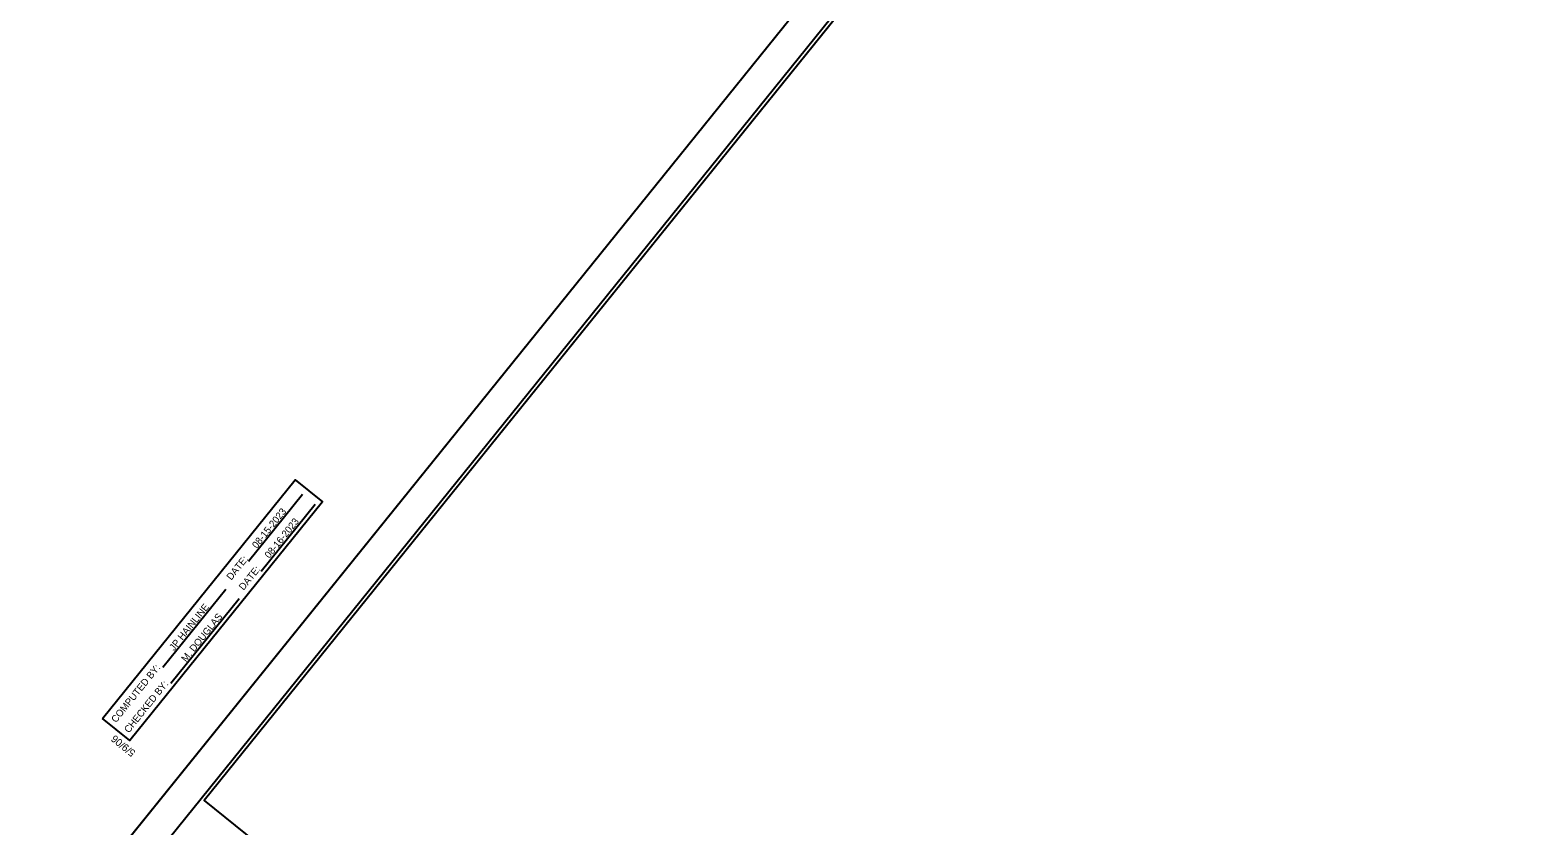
# Model space of a CAD drawing. Extents: x 1489015 to 1490928, y 499814 to 501978.
# Drawn here: x 1489015 to 1490091, y 500601 to 501169 of the extents above; entities that cross this region are included whole.
import ezdxf

# ---------------------------------------------------------------- set-up
doc = ezdxf.new("R2010")
doc.units = 0
for name, color, linetype in [('Sheet Clip Boundary CELL', 7, 'Continuous'), ('Sheet Cutting Line CELL', 7, 'Continuous'), ('Sheet Data Field CELL', 7, 'Continuous'), ('Sheet Plot Border Inside CELL', 7, 'Continuous'), ('Sheet Plot Border Outside CELL', 7, 'Continuous'), ('Sheet Summary Earthwork CELL', 7, 'Continuous')]:
    doc.layers.add(name, color=color, linetype=linetype)

msp = doc.modelspace()

# ---------------------------------------------------------------- linework, layer by layer
at = {"layer": 'Sheet Clip Boundary CELL'}
msp.add_lwpolyline([(1489943.4, 499970.3), (1490726.3, 500941), (1489921.9, 501589.7), (1489139.1, 500619)], close=True, dxfattribs=at)
at = {"layer": 'Sheet Cutting Line CELL'}
msp.add_line((1490072, 501815.5), (1489014.8, 500504.7), dxfattribs=at)
at = {"layer": 'Sheet Plot Border Inside CELL'}
msp.add_lwpolyline([(1490086.6, 501797.9), (1489040.5, 500500.7), (1489861.8, 499838.4), (1490907.9, 501135.6)], close=True, dxfattribs=at)
at = {"layer": 'Sheet Plot Border Outside CELL'}
msp.add_lwpolyline([(1490072, 501815.5), (1489014.8, 500504.7), (1489871.1, 499814.2), (1490928.2, 501125)], close=True, dxfattribs=at)
at = {"layer": 'Sheet Summary Earthwork CELL'}
for p, q in [((1489170.7, 500790), (1489209.3, 500837.8)), ((1489179.8, 500782.9), (1489218.3, 500830.7)), ((1489109.5, 500714.4), (1489154.4, 500770.1)), ((1489115.2, 500702.8), (1489164, 500763.3))]:
    msp.add_line(p, q, dxfattribs=at)
for points in [[(1490080.7, 501786.6), (1489139.1, 500619), (1489956.5, 499959.8), (1490898.1, 501127.5)], [(1489066.5, 500677.6), (1489203.9, 500848), (1489223.4, 500832.4), (1489085.9, 500661.9)]]:
    msp.add_lwpolyline(points, close=True, dxfattribs=at)

# ---------------------------------------------------------------- texts
at = {"layer": 'Sheet Data Field CELL'}
for s, p in [('08-15-2023', (1489176.6, 500798.7)), ('08-16-2023', (1489185.6, 500791.6)), ('JP HAINLINE', (1489117.5, 500725.6)), ('M. DOUGLAS', (1489126.1, 500717.6))]:
    msp.add_text(s, height=5, rotation=51.1156, dxfattribs=at).set_placement(p)
at = {"layer": 'Sheet Summary Earthwork CELL'}
for s, height, rotation, p in [('DATE:', 5, 51.1156, (1489158.4, 500776)), ('DATE:', 5, 51.1156, (1489167.2, 500768.8)), ('COMPUTED BY:', 5, 51.1156, (1489076.1, 500674.2)), ('CHECKED BY:', 5, 51.1156, (1489085.3, 500666.9)), ('5/9/06', 5.25, 141.1156, (1489090.5, 500654))]:
    msp.add_text(s, height=height, rotation=rotation, dxfattribs=at).set_placement(p)

doc.saveas('drawing.dxf')
